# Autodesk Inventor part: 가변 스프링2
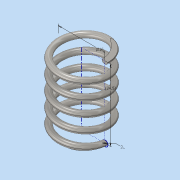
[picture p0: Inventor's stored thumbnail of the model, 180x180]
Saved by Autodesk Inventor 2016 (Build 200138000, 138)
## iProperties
Created: 2018-10
Part Number: 가변 스프링2
Material: 스테인레스 스틸
Document SubType Name: Modeling
Designer: 3sil_cad0123
Density: 8 g/cm^3
Appearance: 반연마
Mass: 6.20711 g
Surface Area: 15.7712 cm^2
Volume: 0.775889 cm^3
Author: 3sil_cad0123
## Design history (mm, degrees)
sketch "스케치1"
  geometry: L1 (0, 0)-(8, 0); L2 (8, 0)-(8, 30.5); L3 (8, 30.5)-(0, 30.5); L4 (0, 30.5)-(0, 0); C1 r 1 at (8, 0)
  constraints: 8 end point, 2 parallel, 1 centre point, 1 coincident, 1 horizontal, 1 perpendicular
  dimensions: "d0" = 16 diameter of L2 L4; "d1" = 2 diameter of C1; "d2" = 30.5 distance of L1.end L2.end (derived)
feature "코일1" pitch "d3" = 10; turns "d5" = 5; dims "d4" = 30.5 (= d2), "d6" = 0, angle "d7" = 90 deg, angle "d8" = 90 deg, "d9" = 0, "d10" = 0
sketch "스케치2"
  geometry: L1 (-7, 0)-(-9, 0) reference; 1 further point
  constraints: 1 horizontal alignment
extrude "돌출1" cut sketch "스케치2" stored distance "d11" = 10; taper "d12" = 0 deg
node "작업 평면2"
sketch "스케치3"
  geometry: L1 (-1, 0)-(1, 0) reference; 1 further point
  constraints: 1 horizontal alignment
extrude "돌출2" cut sketch "스케치3" stored distance "d14" = 10; taper "d15" = 0 deg
node "솔리드1"
node "절단 모서리 투영1"
node "절단 모서리 투영2"
other parameters: "d13" = 90 deg
